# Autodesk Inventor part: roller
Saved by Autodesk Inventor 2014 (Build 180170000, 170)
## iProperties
Created: 2015-06
Part Number: roller
Material: Generic
Document SubType Name: Modeling
Designer: common
Density: 1 g/cm^3
Appearance: Default
Author: common
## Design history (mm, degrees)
node "roller.ipt1"
body "Solid1"
node "Base1"
